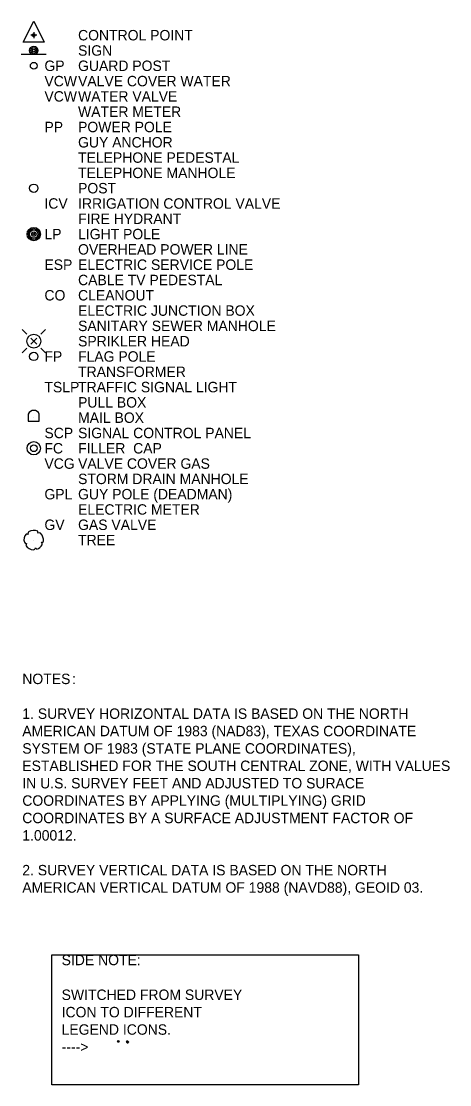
# Model space of a CAD drawing. Extents: x 2250985 to 2256614, y 13788366 to 13792478.
# Drawn here: x 2250985 to 2251601, y 13790192 to 13791721 of the extents above; entities that cross this region are included whole.
import ezdxf

# ---------------------------------------------------------------- set-up
doc = ezdxf.new("R2010")
doc.units = 0
for name, color, linetype in [('Default', 7, 'Continuous'), ('Draft_XS_GoreLimits', 7, 'Continuous'), ('E_Drain_Culvert-Inside', 7, 'Continuous'), ('E_Drain_DitchBottom', 7, 'Continuous'), ('E_Geom_PropertyLine', 7, 'Continuous'), ('E_Inlet_CatchPit', 7, 'Continuous'), ('E_Inlet_Drop_OutsideVault', 7, 'Continuous'), ('E_Inlet_MedianDrop', 7, 'Continuous'), ('E_Rail', 7, 'Continuous'), ('E_Road_Curb_Face', 7, 'Continuous'), ('E_Road_SamplePoint', 7, 'Continuous'), ('E_ROW_Driveway_3D', 7, 'Continuous'), ('E_Terrain_Bank', 7, 'Continuous'), ('E_Util_SanZoning', 7, 'Continuous'), ('Geom_Centerline', 7, 'Continuous')]:
    doc.layers.add(name, color=color, linetype=linetype)

# ---------------------------------------------------------------- blocks, each defined once
blk = doc.blocks.new('traverse_1')
at = {"layer": 'Default'}
for p, q in [((-0.0502, -0.033), (0.0004, 0.0659)), ((0.0004, 0.0659), (0.0498, -0.033)), ((0.0498, -0.033), (-0.0502, -0.033))]:
    blk.add_line(p, q, dxfattribs=at)
blk.add_circle((0, 0), 0.0073, dxfattribs=at)
at = {"layer": 'E_Util_SanZoning'}
for p, q in [((0.0141, 0), (-0.0141, 0)), ((0, 0.0141), (0, -0.0141))]:
    blk.add_line(p, q, dxfattribs=at)
blk = doc.blocks.new('LP')
at = {"layer": 'E_Inlet_CatchPit'}
for radius in [0.128, 0.104, 0.08, 0.0431, 0.0154]:
    blk.add_circle((0, 0), radius, dxfattribs=at)

msp = doc.modelspace()

# ---------------------------------------------------------------- linework, layer by layer
at = {"layer": 'Draft_XS_GoreLimits'}
for radius in [9.56, 4.78]:
    msp.add_circle((2251003, 13791107.1), radius, dxfattribs=at)
at = {"layer": 'E_Drain_Culvert-Inside'}
msp.add_line((2251021, 13791673.1), (2250985, 13791673.1), dxfattribs=at)
for radius in [6, 4.1, 1.83]:
    msp.add_circle((2251003, 13791679.1), radius, dxfattribs=at)
at = {"layer": 'E_Drain_DitchBottom'}
msp.add_circle((2251003, 13791657.1), 4.87, dxfattribs=at)
at = {"layer": 'E_Geom_PropertyLine'}
msp.add_circle((2251003, 13791481.1), 6, dxfattribs=at)
at = {"layer": 'E_Inlet_CatchPit'}
for p, q in [((2251136.5, 13790254), (2251135.9, 13790254.3)), ((2251136.7, 13790252.7), (2251136, 13790252.2)), ((2251137.6, 13790254.7), (2251137.5, 13790255.5)), ((2251137.8, 13790252.1), (2251137.9, 13790251.4)), ((2251138.8, 13790254.2), (2251139.4, 13790254.6)), ((2251138.9, 13790252.9), (2251139.6, 13790252.6))]:
    msp.add_line(p, q, dxfattribs=at)
for centre, radius in [((2251003, 13791415.1), 9.6), ((2251003, 13791415.1), 7.8), ((2251003, 13791415.1), 6), ((2251003, 13791415.1), 3.23), ((2251003, 13791415.1), 1.15), ((2251137.7, 13790253.4), 1.28)]:
    msp.add_circle(centre, radius, dxfattribs=at)
at = {"layer": 'E_Inlet_MedianDrop'}
for p, q in [((2250986.1, 13791278.1), (2250993.1, 13791271)), ((2251020, 13791278.1), (2251012.9, 13791271)), ((2250998.8, 13791265.4), (2251003, 13791261.1)), ((2251003, 13791261.1), (2250998.8, 13791256.9)), ((2251007.3, 13791265.4), (2251003, 13791261.1)), ((2251003, 13791261.1), (2251007.3, 13791256.9)), ((2250993.1, 13791251.2), (2250986.1, 13791244.2)), ((2251012.9, 13791251.2), (2251020, 13791244.2))]:
    msp.add_line(p, q, dxfattribs=at)
msp.add_circle((2251003, 13791261.1), 10, dxfattribs=at)
at = {"layer": 'E_Rail'}
msp.add_circle((2251003, 13791239.1), 6, dxfattribs=at)
at = {"layer": 'E_Road_Curb_Face'}
for p, q in [((2250995.1, 13791156.4), (2250995.1, 13791145.9)), ((2251003, 13791151.1), (2251003, 13791151.1)), ((2251010.9, 13791145.9), (2251010.9, 13791156.4)), ((2250995.1, 13791145.9), (2251010.9, 13791145.9))]:
    msp.add_line(p, q, dxfattribs=at)
msp.add_arc((2251003, 13791153.1), 8.53, 22.5706, 157.4294, dxfattribs=at)
at = {"layer": 'E_Road_SamplePoint'}
msp.add_line((2251003, 13790975.1), (2251003, 13790975.1), dxfattribs=at)
for centre, radius, start, end in [((2250999.9, 13790975.8), 11.1, 136.239, 199.4725), ((2250992.8, 13790977.4), 6.1, 71.3366, 98.5995), ((2250998.3, 13790984.3), 3.68, 135.858, 197.7856), ((2251003, 13790975.1), 13.9, 65.8644, 122.1722), ((2251003, 13790985.6), 6.1, 354.0845, 21.3475), ((2251010.9, 13790981.8), 3.68, 58.606, 120.5335), ((2251003, 13790975.1), 13.9, 351.6313, 44.9243), ((2250992.8, 13790973.7), 3.68, 206.4553, 268.3828), ((2250997.5, 13790966.3), 6.1, 141.9339, 169.1968), ((2251003, 13790975.1), 13.9, 213.692, 268.2244), ((2251003, 13790975.1), 13.9, 289.109, 330.663), ((2251013.1, 13790977.9), 6.1, 279.8472, 307.1101), ((2251011.6, 13790969.3), 3.68, 344.3687, 46.2962), ((2251001.8, 13790964.8), 3.68, 281.8974, 343.8249), ((2251010.2, 13790967.5), 6.1, 217.376, 244.6389)]:
    msp.add_arc(centre, radius, start, end, dxfattribs=at)
at = {"layer": 'E_ROW_Driveway_3D'}
msp.add_lwpolyline([(2251029.1, 13790378.8), (2251469.6, 13790378.8), (2251469.6, 13790191.9), (2251029.1, 13790191.9)], close=True, dxfattribs=at)

# ---------------------------------------------------------------- block references
at = {"layer": 'E_Inlet_CatchPit', "xscale": 10, "yscale": 10}
msp.add_blockref('LP', (2251124.5, 13790254.2), dxfattribs=at)
at = {"layer": 'E_Inlet_Drop_OutsideVault', "xscale": 303.37213868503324, "yscale": 303.37213868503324}
msp.add_blockref('traverse_1', (2251003, 13791701.1), dxfattribs=at)

# ---------------------------------------------------------------- texts
at = {"layer": 'E_ROW_Driveway_3D'}
for s, p in [('SIDE NOTE:', (2251043, 13790363.8)), ('SWITCHED FROM SURVEY ', (2251043, 13790313.8)), ('ICON TO DIFFERENT ', (2251043, 13790288.8)), ('LEGEND ICONS.', (2251043, 13790263.8)), ('---->', (2251043, 13790238.8))]:
    msp.add_text(s, height=15, dxfattribs=at).set_placement(p)
at = {"layer": 'E_Terrain_Bank'}
for s, p in [('  CONTROL POINT', (2251055.5, 13791693.6)), ('  SIGN', (2251055.5, 13791671.6)), ('GP', (2251018.3, 13791649.6)), ('  GUARD POST', (2251055.5, 13791649.6)), ('VCW', (2251018.3, 13791627.6)), ('  VALVE COVER WATER', (2251055.5, 13791627.6)), ('VCW', (2251018.3, 13791605.6)), ('  WATER VALVE', (2251055.5, 13791605.6)), ('  WATER METER', (2251055.5, 13791583.6)), ('PP', (2251018.3, 13791561.6)), ('  POWER POLE', (2251055.5, 13791561.6)), ('  GUY ANCHOR', (2251055.5, 13791539.6)), ('  TELEPHONE PEDESTAL', (2251055.5, 13791517.6)), ('  TELEPHONE MANHOLE', (2251055.5, 13791495.6)), ('  POST', (2251055.5, 13791473.6)), ('ICV', (2251018.3, 13791451.6)), ('  IRRIGATION CONTROL VALVE', (2251055.5, 13791451.6)), ('  FIRE HYDRANT', (2251055.5, 13791429.6)), ('LP', (2251018.3, 13791407.6)), ('  LIGHT POLE', (2251055.5, 13791407.6)), ('  OVERHEAD POWER LINE', (2251055.5, 13791385.6)), ('ESP', (2251018.3, 13791363.6)), ('  ELECTRIC SERVICE POLE', (2251055.5, 13791363.6)), ('  CABLE TV PEDESTAL', (2251055.5, 13791341.6)), ('CO', (2251018.3, 13791319.6)), ('  CLEANOUT', (2251055.5, 13791319.6)), ('  ELECTRIC JUNCTION BOX', (2251055.5, 13791297.6)), ('  SANITARY SEWER MANHOLE', (2251055.5, 13791275.6)), ('  SPRIKLER HEAD', (2251055.5, 13791253.6)), ('FP', (2251018.3, 13791231.6)), ('  FLAG POLE', (2251055.5, 13791231.6)), ('  TRANSFORMER', (2251055.5, 13791209.6)), ('TSLP', (2251018.3, 13791187.6)), ('  TRAFFIC SIGNAL LIGHT', (2251055.5, 13791187.6)), ('  PULL BOX', (2251055.5, 13791165.6)), ('  MAIL BOX', (2251055.5, 13791143.6)), ('SCP', (2251018.3, 13791121.6)), ('  SIGNAL CONTROL PANEL', (2251055.5, 13791121.6)), ('FC', (2251018.3, 13791099.6)), ('  FILLER  CAP', (2251055.5, 13791099.6)), ('VCG', (2251018.3, 13791077.6)), ('  VALVE COVER GAS', (2251055.5, 13791077.6)), ('  STORM DRAIN MANHOLE', (2251055.5, 13791055.6)), ('GPL', (2251018.3, 13791033.6)), ('  GUY POLE (DEADMAN)', (2251055.5, 13791033.6)), ('  ELECTRIC METER', (2251055.5, 13791011.6)), ('GV', (2251018.3, 13790989.6)), ('  GAS VALVE', (2251055.5, 13790989.6)), ('  TREE', (2251055.5, 13790967.6))]:
    msp.add_text(s, height=15, dxfattribs=at).set_placement(p)
at = {"layer": 'Geom_Centerline'}
for s, p in [('NOTES', (2250986.5, 13790768)), (':', (2251058.2, 13790768)), ('1. SURVEY HORIZONTAL DATA IS BASED ON THE NORTH ', (2250986.5, 13790718)), ('AMERICAN DATUM OF 1983 (NAD83), TEXAS COORDINATE ', (2250986.5, 13790693)), ('SYSTEM OF 1983 (STATE PLANE COORDINATES), ', (2250986.5, 13790668)), ('ESTABLISHED FOR THE SOUTH CENTRAL ZONE, WITH VALUES ', (2250986.5, 13790643)), ('IN U.S. SURVEY FEET AND ADJUSTED TO SURACE ', (2250986.5, 13790618)), ('COORDINATES BY APPLYING (MULTIPLYING) GRID ', (2250986.5, 13790593)), ('COORDINATES BY A SURFACE ADJUSTMENT FACTOR OF ', (2250986.5, 13790568)), ('1.00012.', (2250986.5, 13790543)), ('2. SURVEY VERTICAL DATA IS BASED ON THE NORTH ', (2250986.5, 13790493)), ('AMERICAN VERTICAL DATUM OF 1988 (NAVD88), GEOID 03.', (2250986.5, 13790468))]:
    msp.add_text(s, height=15, dxfattribs=at).set_placement(p)

doc.saveas('drawing.dxf')
